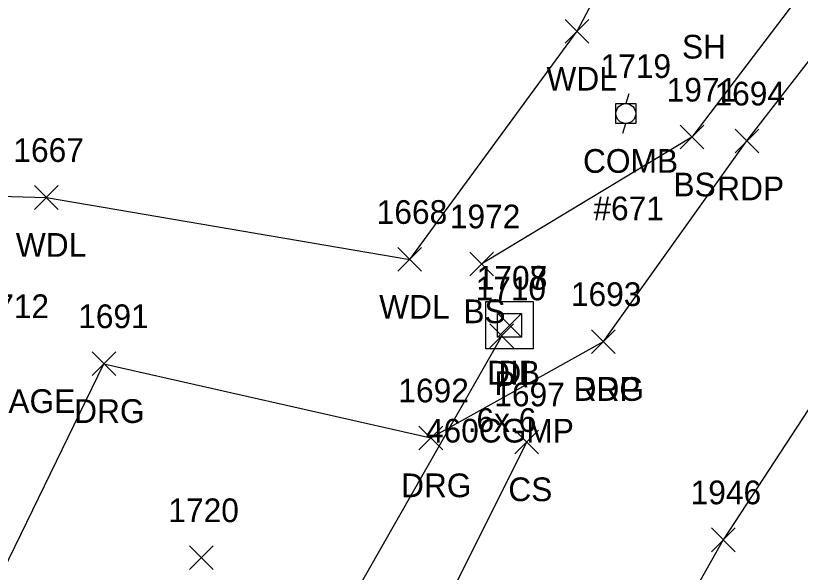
# Model space of a CAD drawing. Extents: x 462930 to 463548, y 29607 to 30453.
# Drawn here: x 463342.46 to 463362.64, y 30161.54 to 30175.85 of the extents above; entities that cross this region are included whole.
import ezdxf

# ---------------------------------------------------------------- set-up
doc = ezdxf.new("R2010")
doc.units = 0
for name, color, linetype in [('D_A', 7, 'Continuous'), ('D_C', 7, 'Continuous'), ('D_I', 7, 'Continuous'), ('D_TIC', 7, 'Continuous'), ('DCP', 7, 'Continuous'), ('DS', 7, 'Continuous'), ('L_A', 7, 'Continuous'), ('L_I', 7, 'Continuous'), ('L_TIC', 7, 'Continuous'), ('LAWA', 7, 'Continuous'), ('LELB', 7, 'Continuous'), ('P_A', 7, 'Continuous'), ('P_I', 7, 'Continuous'), ('P_TIC', 7, 'Continuous'), ('PET', 7, 'Continuous'), ('PRC', 7, 'Continuous'), ('R_A', 7, 'Continuous'), ('R_I', 7, 'Continuous'), ('R_TIC', 7, 'Continuous'), ('RDG', 7, 'Continuous'), ('U_A', 7, 'Continuous'), ('U_C', 7, 'Continuous'), ('U_I', 7, 'Continuous'), ('UP', 7, 'Continuous')]:
    doc.layers.add(name, color=color, linetype=linetype)

msp = doc.modelspace()

# ---------------------------------------------------------------- linework, layer by layer
at = {"layer": 'D_TIC'}
for points in [[(463354.861, 30167.584), (463355.471, 30168.194)], [(463355.471, 30167.584), (463354.861, 30168.194)], [(463354.658, 30167.311), (463355.268, 30167.921)], [(463355.268, 30167.311), (463354.658, 30167.921)]]:
    msp.add_lwpolyline(points, dxfattribs=at)
at = {"layer": 'DCP'}
msp.add_lwpolyline([(463354.963, 30167.616), (463343.04, 30146.69)], dxfattribs=at)
at = {"layer": 'DS'}
for p, q in [((463354.552, 30168.499), (463355.771, 30168.499)), ((463354.552, 30167.28), (463354.552, 30168.499)), ((463355.771, 30168.499), (463355.771, 30167.28)), ((463354.857, 30167.585), (463354.857, 30168.194)), ((463354.857, 30168.194), (463355.466, 30168.194)), ((463355.466, 30168.194), (463355.466, 30167.585)), ((463355.163, 30167.89), (463355.163, 30167.89)), ((463355.163, 30167.89), (463355.163, 30167.89)), ((463355.466, 30167.585), (463354.857, 30167.585)), ((463355.771, 30167.28), (463354.552, 30167.28))]:
    msp.add_line(p, q, dxfattribs=at)
at = {"layer": 'L_TIC'}
for points in [[(463356.594, 30175.142), (463357.204, 30175.752)], [(463357.204, 30175.142), (463356.594, 30175.752)], [(463359.548, 30172.421), (463360.158, 30173.031)], [(463360.158, 30172.421), (463359.548, 30173.031)], [(463342.945, 30170.868), (463343.555, 30171.478)], [(463343.555, 30170.868), (463342.945, 30171.478)], [(463352.291, 30169.276), (463352.901, 30169.886)], [(463352.901, 30169.276), (463352.291, 30169.886)], [(463354.143, 30169.161), (463354.753, 30169.771)], [(463354.753, 30169.161), (463354.143, 30169.771)], [(463355.301, 30164.585), (463355.911, 30165.195)], [(463355.911, 30164.585), (463355.301, 30165.195)], [(463346.929, 30161.607), (463347.539, 30162.217)], [(463347.539, 30161.607), (463346.929, 30162.217)]]:
    msp.add_lwpolyline(points, dxfattribs=at)
at = {"layer": 'LAWA'}
msp.add_lwpolyline([(463334.191, 30153.632), (463326.241, 30157.391), (463319.877, 30160.227), (463314.478, 30162.732), (463317.175, 30171.812), (463324.684, 30170.939), (463329.084, 30171.282), (463333.083, 30171.461), (463343.25, 30171.173), (463352.596, 30169.581), (463356.899, 30175.447), (463361.663, 30184.45), (463356.272, 30186.994), (463347.611, 30186.575), (463333.194, 30190.781), (463330.167, 30185.817), (463328.348, 30182.689), (463321.007, 30182.589)], dxfattribs=at)
at = {"layer": 'LELB'}
for points in [[(463391.469, 30222.327), (463388.015, 30213.37), (463381.524, 30200.3), (463373.809, 30189.987), (463366.273, 30181.173), (463359.853, 30172.726), (463354.448, 30169.466)], [(463355.606, 30164.89), (463349.727, 30153.154)]]:
    msp.add_lwpolyline(points, dxfattribs=at)
at = {"layer": 'P_TIC'}
for points in [[(463360.965, 30172.321), (463361.575, 30172.931)], [(463361.575, 30172.321), (463360.965, 30172.931)], [(463357.271, 30167.164), (463357.881, 30167.774)], [(463357.881, 30167.164), (463357.271, 30167.774)], [(463360.354, 30162.067), (463360.964, 30162.677)], [(463360.964, 30162.067), (463360.354, 30162.677)]]:
    msp.add_lwpolyline(points, dxfattribs=at)
at = {"layer": 'PET'}
msp.add_lwpolyline([(463357.576, 30167.469), (463361.27, 30172.626), (463368.225, 30181.594), (463376.26, 30192.198)], dxfattribs=at)
at = {"layer": 'PRC'}
msp.add_lwpolyline([(463399.789, 30246.987), (463397.991, 30230.027), (463395.304, 30217.172), (463391.095, 30206.312), (463384.492, 30195.113), (463376.573, 30184.227), (463367.848, 30173.371), (463360.659, 30162.372), (463353.283, 30149.309)], dxfattribs=at)
at = {"layer": 'R_TIC'}
for points in [[(463357.271, 30167.164), (463357.881, 30167.774)], [(463357.881, 30167.164), (463357.271, 30167.774)], [(463344.424, 30166.596), (463345.034, 30167.206)], [(463345.034, 30166.596), (463344.424, 30167.206)], [(463352.833, 30164.687), (463353.443, 30165.297)], [(463353.443, 30164.687), (463352.833, 30165.297)]]:
    msp.add_lwpolyline(points, dxfattribs=at)
at = {"layer": 'RDG'}
msp.add_lwpolyline([(463347.931, 30153.415), (463337.62, 30154.896), (463328.703, 30158.04), (463317.438, 30162.728), (463318.8, 30166.246), (463327.27, 30162.794), (463340.451, 30158.117), (463344.729, 30166.901), (463353.138, 30164.992), (463357.576, 30167.469)], dxfattribs=at)
at = {"layer": 'UP'}
for p, q in [((463358.23, 30173.84), (463358.154, 30173.586)), ((463357.9, 30173.078), (463357.9, 30173.586)), ((463357.9, 30173.586), (463358.408, 30173.586)), ((463358.408, 30173.586), (463358.408, 30173.078)), ((463358.154, 30173.332), (463358.154, 30173.332)), ((463358.408, 30173.078), (463357.9, 30173.078)), ((463358.078, 30172.824), (463358.154, 30173.078))]:
    msp.add_line(p, q, dxfattribs=at)
msp.add_circle((463358.154, 30173.332), 0.254, dxfattribs=at)

# ---------------------------------------------------------------- texts
at = {"layer": 'D_A'}
for s, height, p in [('DIB', 0.6096, (463354.588, 30166.365)), ('DI', 0.6096, (463354.875, 30166.366)), ('P', 0.61, (463354.773, 30166.092))]:
    msp.add_text(s, height=height, dxfattribs=at).set_placement(p)
at = {"layer": 'D_C'}
for s, p in [('.6x.6', (463354.085, 30165.147)), ('460CGMP', (463353.012, 30164.873))]:
    msp.add_text(s, height=0.6096, dxfattribs=at).set_placement(p)
at = {"layer": 'D_I'}
for s, p in [('1707', (463354.318, 30168.804)), ('1708', (463354.321, 30168.803)), ('1710', (463354.289, 30168.53))]:
    msp.add_text(s, height=0.6096, dxfattribs=at).set_placement(p)
at = {"layer": 'L_A'}
for s, p in [('SH', (463359.598, 30174.746)), ('WDL', (463356.112, 30173.923)), ('BS', (463359.378, 30171.202)), ('WDL', (463342.463, 30169.649)), ('WDL', (463351.809, 30168.057)), ('BS', (463353.973, 30167.942)), ('GARAGE', (463340.505, 30165.634)), ('CS', (463355.131, 30163.366))]:
    msp.add_text(s, height=0.6096, dxfattribs=at).set_placement(p)
at = {"layer": 'L_I'}
for s, p in [('1971', (463359.205, 30173.64)), ('1667', (463342.4, 30172.087)), ('1668', (463351.746, 30170.495)), ('1972', (463353.627, 30170.38)), ('1712', (463341.503, 30168.072)), ('1697', (463354.771, 30165.804)), ('1720', (463346.387, 30162.826))]:
    msp.add_text(s, height=0.6096, dxfattribs=at).set_placement(p)
at = {"layer": 'P_A'}
for p in [(463360.504, 30171.102), (463356.81, 30165.945)]:
    msp.add_text('RDP', height=0.6096, dxfattribs=at).set_placement(p)
at = {"layer": 'P_I'}
for s, p in [('1694', (463360.435, 30173.54)), ('1693', (463356.741, 30168.383)), ('1946', (463359.821, 30163.286))]:
    msp.add_text(s, height=0.6096, dxfattribs=at).set_placement(p)
at = {"layer": 'R_A'}
for p in [(463356.81, 30165.945), (463343.963, 30165.377), (463352.372, 30163.468)]:
    msp.add_text('DRG', height=0.6096, dxfattribs=at).set_placement(p)
at = {"layer": 'R_I'}
for s, p in [('1693', (463356.741, 30168.383)), ('1691', (463344.067, 30167.815)), ('1692', (463352.303, 30165.906))]:
    msp.add_text(s, height=0.6096, dxfattribs=at).set_placement(p)
at = {"layer": 'U_A'}
msp.add_text('COMB', height=0.6096, dxfattribs=at).set_placement((463357.052, 30171.808))
at = {"layer": 'U_C'}
msp.add_text('#671', height=0.6096, dxfattribs=at).set_placement((463357.319, 30170.589))
at = {"layer": 'U_I'}
msp.add_text('1719', height=0.6096, dxfattribs=at).set_placement((463357.504, 30174.246))

doc.saveas('drawing.dxf')
